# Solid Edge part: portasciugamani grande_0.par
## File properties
Last saved by: i.fialdini
Revision: 62
Tipo di contenuto documento: 0
Accuracy: 0.990
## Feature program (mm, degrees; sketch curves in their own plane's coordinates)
body "unnamed Body 1"
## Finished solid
Body 1: solid body, 3 faces, 4 edges, 4 vertices.
  Faces by surface: cylinder 3
  Edges by curve: ellipse 4
Bounding box of the edges (mm): 690.000 x 21.000 x 21.000, from (-345, 167.5, -167.5) to (345, 188.5, -146.5).
Cylindrical faces by radius (mm): R10.5 x3
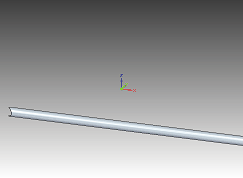
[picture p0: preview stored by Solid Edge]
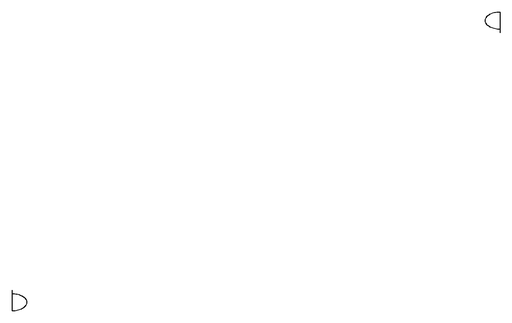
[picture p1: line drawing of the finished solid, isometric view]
